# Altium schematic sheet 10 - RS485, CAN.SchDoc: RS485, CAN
size A3; PageSetup: Record=PageOptions¦CenterHorizontal=True¦CenterVertical=True¦PrintScale=0.70¦XCorrection=1.00¦YCorrection=1.00¦PrintKind=0¦BorderSize=5000000¦LeftOffset=0¦BottomOffset=0¦Orientation=2¦PaperLength=4200¦PaperWidth=2970¦Scale=100¦PaperSource=7¦PrintQuality=600¦MediaType=1¦DitherType=10¦PaperKind=A4¦PrintScaleMode=1; Author: Juan Anzola; SheetNumber: 10; SheetTotal: 21
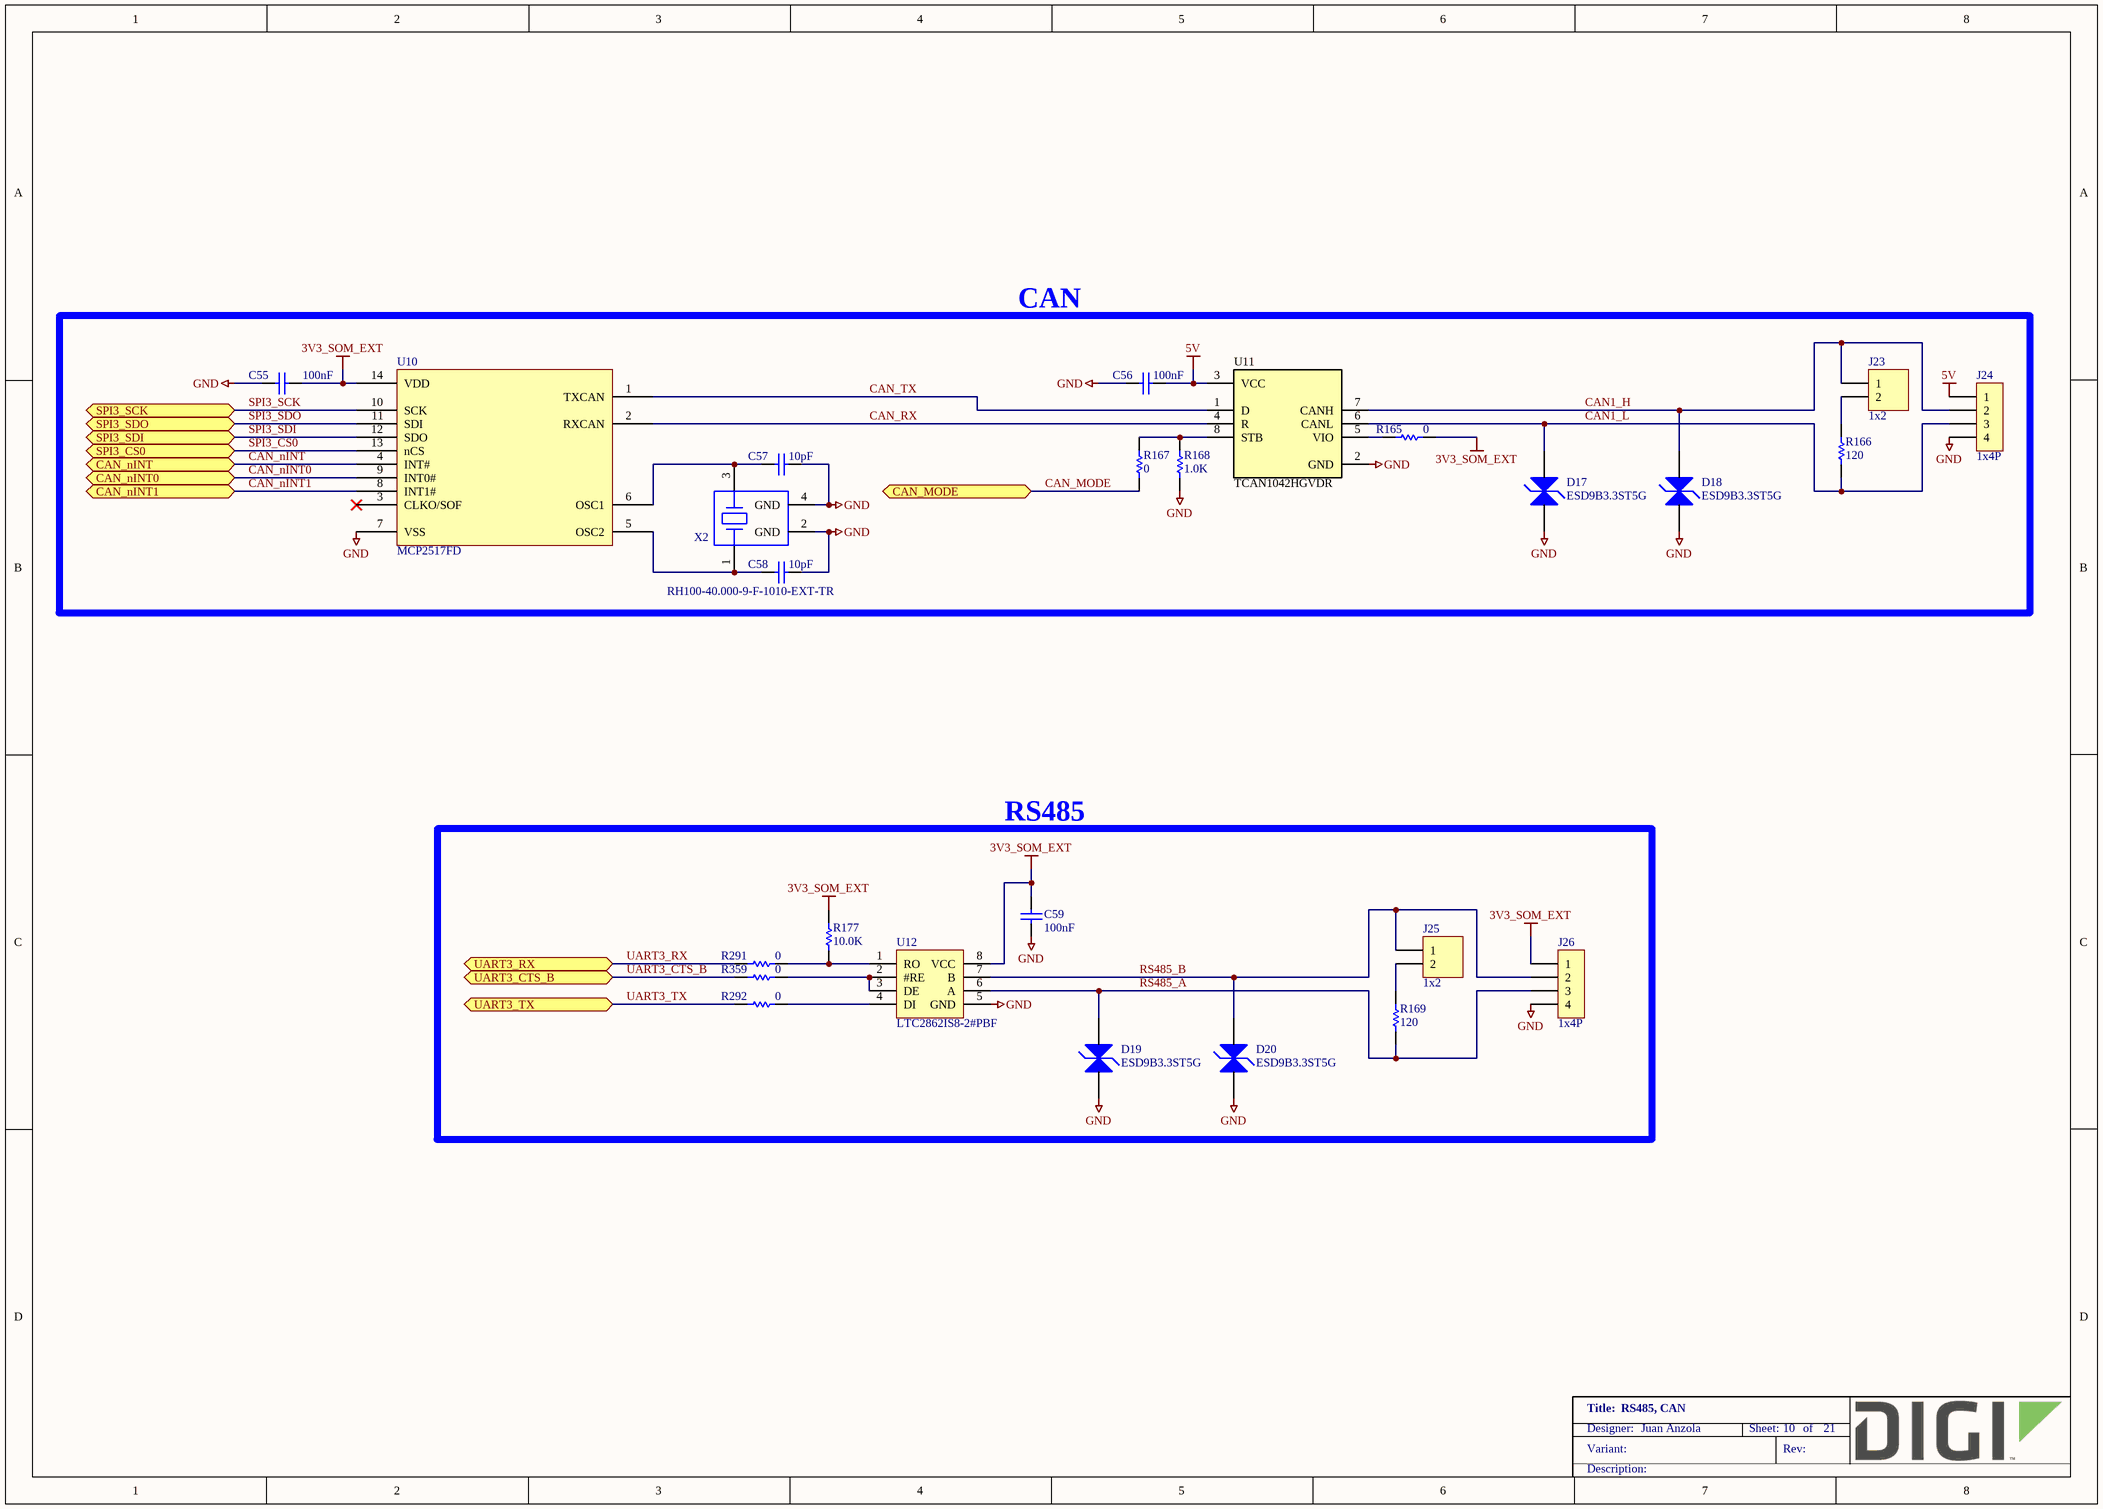
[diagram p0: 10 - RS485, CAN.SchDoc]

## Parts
C55  100nF  [CAPC1005X55N]
C56  100nF  [CAPC1005X55N]
C57  10pF  [CAPC1005X55N]
C58  10pF  [CAPC1005X55N]
C59  100nF  [CAPC1005X55N]
D17  ESD9B3.3ST5G  [SODFL1006X43AN12]
D18  ESD9B3.3ST5G  [SODFL1006X43AN12]
D19  ESD9B3.3ST5G  [SODFL1006X43AN12]
D20  ESD9B3.3ST5G  [SODFL1006X43AN12]
J23  1x2  [FCI_68002-102HLF]
J24  1x4P  [HDRV4W64P254_4X1_1016X248H1067]
J25  1x2  [FCI_68002-102HLF]
J26  1x4P  [HDRV4W64P254_4X1_1016X248H1067]
R165  0  [RESC1005X40N]
R166  120  [RESC1005X40N]
R167  0  [RESC1005X40N]
R168  1.0K  [RESC1005X40N]
R169  120  [RESC1005X40N]
R177  10.0K  [RESC1005X40N]
R291  0  [RESC1005X40N]
R292  0  [RESC1005X40N]
R359  0  [RESC1005X40N]
U10  MCP2517FD  [SOIC127P600X175-14N]
U11  TCAN1042HGVDR  [SOIC127P600X175-8N]
U12  LTC2862IS8-2#PBF  [SOIC127P600X175-8N]
X2  RH100-40.000-9-F-1010-EXT-TR  [OSCCC320X250X71N]

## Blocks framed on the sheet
RS485: C59 D19 D20 J25 J26 R169 R177 R291 R292 R359 U12

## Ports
CAN_MODE (bidir), CAN_nINT0 (bidir), CAN_nINT1 (bidir), CAN_nINT (bidir), SPI3_CS0 (bidir), SPI3_SCK (bidir), SPI3_SDI (bidir), SPI3_SDO (bidir), UART3_CTS_B (bidir), UART3_RX (bidir), UART3_TX (bidir)

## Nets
3V3_SOM_EXT: C55.1 C59.2 J26.1 R165.2 R177.2 U10.14(VDD) U12.8(VCC)
5V: C56.1 J24.1 U11.3(VCC)
GND: C55.2 C56.2 C57.1 C58.1 C59.1 D17.1 D18.1 D19.1 D20.1 J24.4 J26.4 R168.1 U10.7(VSS) U11.2(GND) U12.5(GND) X2.2(GND) X2.4(GND)
CAN1_H: D18.2 J23.1 J24.2 U11.7(CANH)
CAN1_L: D17.2 J24.3 R166.1 U11.6(CANL)
CAN_MODE: R167.1 ; port CAN_MODE
CAN_nINT: U10.4(INT#) ; port CAN_nINT
CAN_nINT0: U10.9(INT0#) ; port CAN_nINT0
CAN_nINT1: U10.8(INT1#) ; port CAN_nINT1
CAN_RX: U10.2(RXCAN) U11.4(R)
CAN_TX: U10.1(TXCAN) U11.1(D)
RS485_A: D19.2 J26.3 R169.1 U12.6(A)
RS485_B: D20.2 J25.1 J26.2 U12.7(B)
SPI3_CS0: U10.13(nCS) ; port SPI3_CS0
SPI3_SCK: U10.10(SCK) ; port SPI3_SCK
SPI3_SDI: U10.12(SDO) ; port SPI3_SDI
SPI3_SDO: U10.11(SDI) ; port SPI3_SDO
UART3_CTS_B: R359.1 ; port UART3_CTS_B
UART3_RX: R291.1 ; port UART3_RX
UART3_TX: R292.1 ; port UART3_TX
NetC57_2: C57.2 U10.6(OSC1) X2.3
NetC58_2: C58.2 U10.5(OSC2) X2.1
NetJ23_2: J23.2 R166.2
NetJ25_2: J25.2 R169.2
NetR165_1: R165.1 U11.5(VIO)
NetR167_2: R167.2 R168.2 U11.8(STB)
NetR177_1: R177.1 R291.2 U12.1(RO)
NetR292_2: R292.2 U12.4(DI)
NetR359_2: R359.2 U12.2(#RE) U12.3(DE)

Not connected (* = marked no-connect by the designer): U10 3(CLKO/SOF)*

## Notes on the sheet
- CAN
- (near U10) CAN

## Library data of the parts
C55 C56 C59 = 1000006: CAP 100nF 16V 10% X7R 0402; Part_Type: Capacitor; Manufacturer: Murata; Manufacturer_Part_Number: GRM155R71C104KA88D; Component_Life_Cycle_State: CAD Reviewed; Area: 0.95; Project: KITT; Tolerance: 10; Digi_PN: 14050552
C57 C58 = 1001541: CAP CER 10PF 50V 5% NP0 0402; Part_Type: Capacitor; Manufacturer: Murata; Manufacturer_Part_Number: GRM1555C1H100JA01D; Note: 14050750 = Digi No. for GE WDNU; Digi_PN: 14050362; Component_Life_Cycle_State: Reviewed; Area: 0,95; Project: KITT v0.4; Tolerance: 5; Temp_Coef: C0G, NP0
D17-D20 = 1001637: TVS DIODE 3.3VWM SOD923; Part_Type: Diodes; Manufacturer: On Semiconductor; Digi_PN: 17050883; Component_Life_Cycle_State: Reviewed; Area: 1,01
J23 J25 = 1001128: CONN HEADER 2POS .100" SGL GOLD; Part_Type: Connector; Manufacturer: Samtec; Manufacturer_Part_Number: TSW-102-07-G-S; Digi_PN: 00120002; Component_Life_Cycle_State: Reviewed; Area: 12,9032
J24 J26 = 1002743: CONN HEADER VERT 4POS 2.54MM; Part_Type: Connector; Manufacturer: Semtech; Manufacturer_Part_Number: TSW-104-14-G-S; Digi_PN: 18050278; Component_Life_Cycle_State: Reviewed; Area: 31,77
R165 = 1000076: RES 0.0 OHM 1/10W 0402 SMD; Part_Type: Resistor; Manufacturer: Panasonic - ECG; Manufacturer_Part_Number: ERJ-2GE0R00X; Component_Life_Cycle_State: Proven; Area: 0.95; Project: Adjustable Foundation; Power_WV_SRF: 10; Digi_PN: 13050387
R166 R169 = 1001158: RES 120 OHM 1/16W 1% 0402 SMD; Part_Type: Resistor; Manufacturer: Yageo; Manufacturer_Part_Number: RC0402FR-07120RL; Digi_PN: 13050832; Component_Life_Cycle_State: Reviewed; Area: 0.95; Project: CCWMX6_SBC board; Note: 13051102 = Digi No. for GE WDNU
R167 = 1000076: RES 0.0 OHM 1/10W 0402 SMD; Part_Type: Resistor; Manufacturer: Panasonic - ECG; Manufacturer_Part_Number: ERJ-2GE0R00X; Digi_PN: 13050387; Component_Life_Cycle_State: Proven; Area: 0,95; Project: Adjustable Foundation; Power_WV_SRF: 10
R168 = 1000079: RES 1.00K OHM 1/10W 1% 0402 SMD; Part_Type: Resistor; Manufacturer: Panasonic - ECG; Manufacturer_Part_Number: ERJ-2RKF1001X; Digi_PN: 13051085; Component_Life_Cycle_State: Proven; Area: 0,95; Project: Adjustable Foundation; Power_WV_SRF: 10
R177 = 1000537: RES 10.0K OHM 1/10W 1% 0402 SMD; Part_Type: Resistor; Manufacturer: Panasonic - ECG; Manufacturer_Part_Number: ERJ-2RKF1002X; Component_Life_Cycle_State: CAD Reviewed; Area: 0.95; Project: KITT; Power_WV_SRF: 100; Digi_PN: 13051084
R291 R292 R359 = 1000076: RES 0.0 OHM 1/10W 0402 SMD; Part_Type: Resistor; Manufacturer: Panasonic - ECG; Manufacturer_Part_Number: ERJ-2GE0R00X; Digi_PN: 13050387; Component_Life_Cycle_State: Proven; Area: 0,95; Power_WV_SRF: 10
U10 = 1002729: IC CANBUS CONTROLLER SPI 14SOIC; Manufacturer: Microchip; Manufacturer_Part_Number: MCP2517FD-H/SL; Digi_PN: 16000201; Component_Life_Cycle_State: Reviewed; Area: 69,04
U11 = 1002681: IC CAN TRANSEIVER HS 8SOIC; Manufacturer: Texas Instruments; Digi_PN: 16000166; Component_Life_Cycle_State: Pending; Area: 20; Project: DIGI CC8X SOM
U12 = 1001420: IC TRANSCEIVER RS485 8-SOIC; Manufacturer: Linear Technology; Digi_PN: 16052092; Component_Life_Cycle_State: Reviewed; Area: 34.75; Project: E-Gear Gateway v0.1
X2 = 1002203: CRYSTAL 40.0000MHz 9pF -40°C - 85°C DFN LCC; Part_Type: Crystals-Oscillators; Manufacturer: Raltron; Digi_PN: 20000303; Component_Life_Cycle_State: Reviewed; Area: 14,92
